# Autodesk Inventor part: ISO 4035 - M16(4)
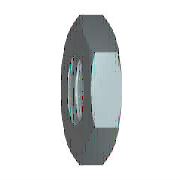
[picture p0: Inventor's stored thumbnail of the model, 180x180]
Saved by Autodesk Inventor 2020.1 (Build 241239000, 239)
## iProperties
Created: 2019-01
Part Number: ISO 4035 - M16(4)
Material: Edelstahl, 440C
Description: Sechskantmuttern, niedrige Form (mit Fase) - Produktklasse A und B
Document SubType Name: Modeling
Standard: ISO 4035
Designer: lutzd
Standard Revision: Fourth edition 2012-12-15
Standards Organization: ISO
Language: de-DE
Size Designation: M16
Categories: <MemberInstance><Categories><Category DisplayName="Verbindungselemente" InternalName="e4da775c-781d-43d5-af7c-5136215cf5a6" Mnemonic="FSTN"><Category DisplayNam
Mass: 20.6371 g
Surface Area: 15.6937 cm^2
Volume: 2.66285 cm^3
Density: 7.75 g/cm^3
Appearance: Halbpoliert
IsCustomPart: 0
Author: lutzd
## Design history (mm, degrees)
workaxis "Work Axis1"
workplane "Work Plane1"
sketch "Skizze1"
  geometry: L1 (-13.856, 0)-(-6.928, 12); L2 (-6.928, 12)-(6.928, 12); L3 (6.928, 12)-(13.856, 0); L4 (13.856, 0)-(6.928, -12); L5 (6.928, -12)-(-6.928, -12); L6 (-6.928, -12)-(-13.856, 0); 2 further points
  constraints: 12 end point, 1 coincident, 1 horizontal, 11 other
  dimensions: "d0" = 27.71281 distance of L3.end L1.start (= 1.1547 x SW)
extrude "Körper" new body sketch "Skizze1" distance "d1" = 8 (= KOH); taper "d2" = 0 deg
sketch "Skizze2"
  geometry: L1 (0, 6.928)-(0, 13.856) reference; L2 (0, 13.856)-(8, 13.856) reference; L3 (8, 6.928)-(8, 13.856) reference; L4 (-1.6, 0)-(9.6, 0) reference; L5 (1.505, 13.856)-(0, 11.25); L6 (6.495, 13.856)-(8, 11.25)
  constraints: 4 end point, 4 point on line
  dimensions: "d3" = 30 deg angle of L1 L5 (= ANG1); "d4" = 30 deg angle of L3 L6 (= ANG2); "d5" = 22.5 diameter of L5.end L4 (= SW0); "d6" = 22.5 diameter of L6.end L4 (= SW01)
revolve "Fase1" stored, may be unused: angle "d7" = 90 deg
sketch "Skizze3"
  geometry: 4 further points
  constraints: 1 coincident, 1 other
hole "Gewinde" sketch "Skizze3" diameter "d25" = 13.835; stored, may be unused: countersink angle "d29" = 82 deg, drill point angle "d31" = 118 deg; dims "d26" = 6, "d27" = 4, "d28" = 2, "d30" = 8
body "Solid1"
chamfer "Fase2" distance "d8" = 1.08253 (= -0.5 x GD1 + 0.5 x NND); stored, may be unused: angle "d9" = 30 deg, second distance "d40" = 1.08253 (= -0.5 x GD1 + 0.5 x NND)
chamfer "Fase3" distance "d10" = 1.08253 (= -0.5 x GD1 + 0.5 x NND); stored, may be unused: angle "d11" = 30 deg, second distance "d41" = 1.08253 (= -0.5 x GD1 + 0.5 x NND)
other parameters: "ANG1" = 30 deg [user parameter; used in 1 equation term], "ANG2" = 30 deg [user parameter; used in 1 equation term], "NND" = 16 [user parameter; used in 4 equation terms], "KOH" = 8 [user parameter; used in 1 equation term], "SW" = 24 [user parameter; used in 2 equation terms], "SW0" = 22.5 [user parameter; used in 2 equation terms], "SW01" = 22.5 (= SW0) [user parameter; used in 1 equation term], "GD1" = 13.83494 (computed from THREADDIA, PTC, TOA) [user parameter; used in 4 equation terms], "d13" = 0, "d14" = 0, "d39" = 0, "d42" = 0, "GUL" = 1.08253 (= 0.541266 x PTC) [user parameter], "TPU" = 5 (computed from PTC) [user parameter], "THREADDIA" = 16 [user parameter; used in 1 equation term], "TOA" = 30 deg [user parameter; used in 1 equation term], "PTC" = 2 [user parameter; used in 4 equation terms], "E0" = 27.72 (= 1.155 x SW) [user parameter], "GAL" = 1.08253 (= 0.541266 x PTC) [user parameter]
